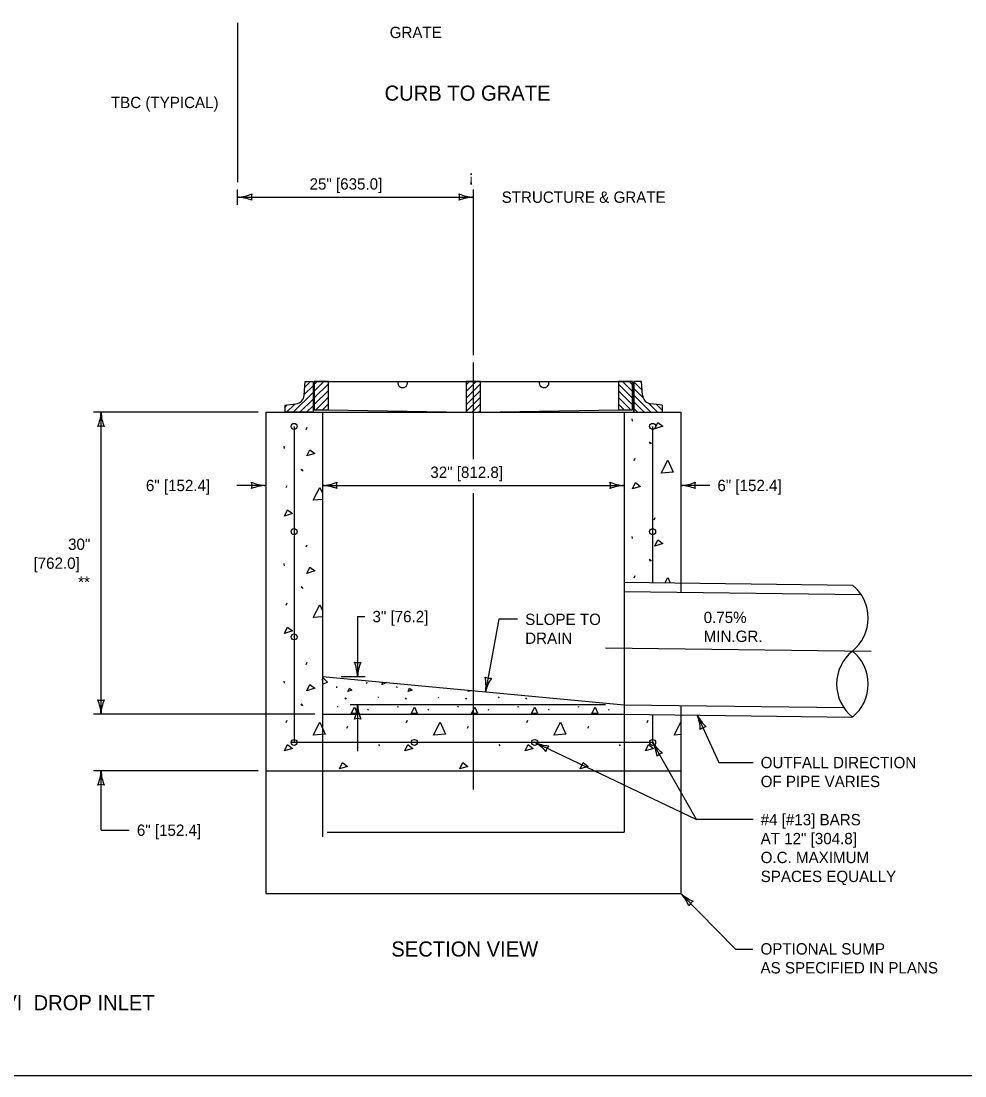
# Model space of a CAD drawing. Extents: x 49991.4 to 50041.6, y 49987.6 to 50011.4.
# Drawn here: x 50003.39 to 50008.39, y 49987.8 to 49993.39 of the extents above; entities that cross this region are included whole.
import ezdxf

# ---------------------------------------------------------------- set-up
doc = ezdxf.new("R2010")
doc.units = 0
for name, color, linetype in [('Level 1', 7, 'Continuous'), ('Level 2', 7, 'Continuous'), ('Level 3', 7, 'Continuous'), ('Level 4', 7, 'Continuous'), ('Level 5', 7, 'Continuous')]:
    doc.layers.add(name, color=color, linetype=linetype)

msp = doc.modelspace()

# ---------------------------------------------------------------- linework, layer by layer
at = {"layer": 'Level 1'}
for p, q in [((50004.5386, 49993.3789), (50004.5386, 49992.5353)), ((50004.8923, 49991.4098), (50004.9386, 49991.4562)), ((50004.8953, 49991.4482), (50004.9254, 49991.4783)), ((50004.9449, 49991.4783), (50006.6324, 49991.4783)), ((50004.9449, 49991.4266), (50004.9966, 49991.4783)), ((50004.9449, 49991.4619), (50004.9613, 49991.4783)), ((50004.9449, 49991.3912), (50005.0199, 49991.4662)), ((50005.4136, 49991.4783), (50005.4136, 49991.4783)), ((50005.7511, 49991.4262), (50005.8033, 49991.4783)), ((50005.7511, 49991.4615), (50005.7679, 49991.4783)), ((50005.7511, 49991.3908), (50005.8261, 49991.4658)), ((50006.1636, 49991.4783), (50006.1636, 49991.4783)), ((50006.5574, 49991.465), (50006.6324, 49991.39)), ((50006.5794, 49991.4783), (50006.6324, 49991.4254)), ((50006.6148, 49991.4783), (50006.6324, 49991.4607)), ((50006.6386, 49991.3158), (50006.6386, 49991.4783)), ((50006.6387, 49991.4773), (50006.6832, 49991.4328)), ((50006.6387, 49991.4419), (50006.6886, 49991.3921)), ((50006.673, 49991.4783), (50006.6802, 49991.4711)), ((50004.8336, 49991.3158), (50004.9386, 49991.4208)), ((50004.869, 49991.3158), (50004.9386, 49991.3855)), ((50004.9449, 49991.3559), (50005.0199, 49991.4309)), ((50004.9527, 49991.3283), (50005.0199, 49991.3955)), ((50005.7511, 49991.3555), (50005.8261, 49991.4305)), ((50005.7511, 49991.3201), (50005.8261, 49991.3951)), ((50006.5574, 49991.4297), (50006.6324, 49991.3547)), ((50006.5574, 49991.3943), (50006.6233, 49991.3283)), ((50006.6387, 49991.4066), (50006.7294, 49991.3158)), ((50004.7886, 49991.3529), (50004.8478, 49991.3597)), ((50004.7886, 49991.3415), (50004.8014, 49991.3543)), ((50004.7886, 49991.3529), (50004.7886, 49991.3158)), ((50004.7983, 49991.3158), (50004.8414, 49991.359)), ((50004.9043, 49991.3158), (50004.9386, 49991.3501)), ((50004.9881, 49991.3283), (50005.0199, 49991.3601)), ((50005.0199, 49991.3283), (50005.7511, 49991.3158)), ((50005.7822, 49991.3158), (50005.8261, 49991.3598)), ((50005.8261, 49991.3158), (50006.5574, 49991.3283)), ((50006.5574, 49991.359), (50006.588, 49991.3283)), ((50006.6387, 49991.3712), (50006.6941, 49991.3158)), ((50006.6387, 49991.3359), (50006.6587, 49991.3158)), ((50006.7174, 49991.3633), (50006.7648, 49991.3158)), ((50006.7598, 49991.3562), (50006.7886, 49991.3274)), ((50006.7886, 49991.3529), (50006.7886, 49991.3158)), ((50004.6886, 49991.3158), (50006.8886, 49991.3158)), ((50004.6886, 49991.3158), (50004.6886, 49989.7158)), ((50004.8252, 49991.3158), (50004.8253, 49991.3162)), ((50004.9886, 49991.3158), (50004.9886, 49989.7158)), ((50005.8175, 49991.3158), (50005.8261, 49991.3244)), ((50006.5886, 49991.3158), (50006.5886, 49989.7158)), ((50006.6286, 49991.2799), (50006.6299, 49991.2679)), ((50006.8886, 49991.3158), (50006.8886, 49990.362)), ((50004.8386, 49991.2408), (50004.8386, 49989.5665)), ((50004.9028, 49991.2238), (50004.9081, 49991.2358)), ((50006.7386, 49991.2408), (50006.7386, 49990.4139)), ((50006.7195, 49991.1588), (50006.7248, 49991.1508)), ((50004.7839, 49991.1357), (50004.7852, 49991.1237)), ((50006.7248, 49991.1558), (50006.7302, 49991.1478)), ((50006.6409, 49991.0601), (50006.6462, 49991.072)), ((50004.8748, 49991.0147), (50004.8801, 49991.0067)), ((50004.8801, 49991.0116), (50004.8855, 49991.0036)), ((50004.7962, 49990.9159), (50004.8015, 49990.9279)), ((50004.9886, 49990.8535), (50004.9401, 49990.8493)), ((50006.7475, 49990.7457), (50006.7528, 49990.7577)), ((50006.6286, 49990.6576), (50006.6299, 49990.6457)), ((50004.9028, 49990.6016), (50004.9081, 49990.6136)), ((50004.7839, 49990.5135), (50004.7852, 49990.5015)), ((50006.7195, 49990.5366), (50006.7248, 49990.5286)), ((50006.7248, 49990.5335), (50006.7302, 49990.5256)), ((50006.6409, 49990.4378), (50006.6462, 49990.4498)), ((50004.8748, 49990.3924), (50004.8801, 49990.3845)), ((50004.8801, 49990.3894), (50004.8855, 49990.3814)), ((50006.5886, 49990.4159), (50007.7977, 49990.4001)), ((50006.5886, 49990.3659), (50007.8438, 49990.3495)), ((50004.7962, 49990.2937), (50004.8015, 49990.3057)), ((50004.9886, 49990.2312), (50004.9401, 49990.2271)), ((50004.9028, 49989.9794), (50004.9081, 49989.9913)), ((50004.7839, 49989.8913), (50004.7852, 49989.8793)), ((50004.9886, 49989.9158), (50006.5886, 49989.7658)), ((50005.2234, 49989.8787), (50005.226, 49989.8847)), ((50005.3044, 49989.8719), (50005.3064, 49989.8861)), ((50005.3303, 49989.8838), (50005.305, 49989.8721)), ((50005.0627, 49989.862), (50005.0633, 49989.856)), ((50005.3817, 49989.862), (50005.3824, 49989.856)), ((50005.7615, 49989.8361), (50005.7649, 49989.8431)), ((50005.7794, 49989.8417), (50005.7615, 49989.8361)), ((50004.8748, 49989.7702), (50004.8801, 49989.7622)), ((50004.8801, 49989.7672), (50004.8855, 49989.7592)), ((50005.1081, 49989.8015), (50005.1108, 49989.7975)), ((50005.1108, 49989.8), (50005.1135, 49989.796)), ((50005.284, 49989.8015), (50005.2866, 49989.8075)), ((50005.4272, 49989.8015), (50005.4298, 49989.7975)), ((50005.4298, 49989.8), (50005.4325, 49989.796)), ((50005.603, 49989.8015), (50005.6057, 49989.8075)), ((50005.7462, 49989.8015), (50005.7489, 49989.7975)), ((50005.7489, 49989.8), (50005.7515, 49989.796)), ((50005.922, 49989.8015), (50005.9247, 49989.8075)), ((50006.0652, 49989.8015), (50006.0679, 49989.7975)), ((50006.0679, 49989.8), (50006.0706, 49989.796)), ((50006.5886, 49989.7658), (50007.7517, 49989.7506)), ((50006.8886, 49989.7619), (50006.8886, 49989.4158)), ((50004.6886, 49989.7158), (50004.6886, 49989.4158)), ((50004.9886, 49989.7158), (50006.5886, 49989.7158)), ((50005.0688, 49989.7521), (50005.0715, 49989.7581)), ((50005.23, 49989.7368), (50005.2327, 49989.7428)), ((50005.3879, 49989.7521), (50005.3905, 49989.7581)), ((50005.5491, 49989.7368), (50005.5517, 49989.7428)), ((50005.7069, 49989.7521), (50005.7096, 49989.7581)), ((50005.8681, 49989.7368), (50005.8708, 49989.7428)), ((50006.0259, 49989.7521), (50006.0286, 49989.7581)), ((50006.1871, 49989.7368), (50006.1898, 49989.7428)), ((50006.345, 49989.7521), (50006.3476, 49989.7581)), ((50006.5062, 49989.7368), (50006.5088, 49989.7428)), ((50006.5886, 49989.7158), (50007.7977, 49989.7)), ((50006.7386, 49989.7139), (50006.7386, 49989.5665)), ((50004.7962, 49989.6715), (50004.8015, 49989.6835)), ((50005.1186, 49989.6409), (50005.1239, 49989.6528)), ((50005.4343, 49989.6715), (50005.4396, 49989.6835)), ((50005.7566, 49989.6409), (50005.762, 49989.6528)), ((50006.0723, 49989.6715), (50006.0777, 49989.6835)), ((50006.3947, 49989.6409), (50006.4, 49989.6528)), ((50006.7104, 49989.6715), (50006.7157, 49989.6835)), ((50006.853, 49989.6049), (50006.8888, 49989.6727)), ((50006.8888, 49989.6078), (50006.8543, 49989.6049)), ((50004.8192, 49989.5665), (50006.7386, 49989.5665)), ((50005.2851, 49989.5556), (50005.2904, 49989.5476)), ((50005.9231, 49989.5556), (50005.9285, 49989.5476)), ((50006.5612, 49989.5556), (50006.5665, 49989.5476)), ((50004.6886, 49989.4158), (50006.8886, 49989.4158))]:
    msp.add_line(p, q, dxfattribs=at)
for points in [[(49999.3835, 49998.9992), (50016.7501, 49998.9992), (50016.7501, 49987.7988), (49999.3835, 49987.7988)], [(50004.9449, 49991.4783), (50004.9449, 49991.3283), (50005.0199, 49991.3283), (50005.0199, 49991.4783)], [(50005.7511, 49991.4783), (50005.7511, 49991.3158), (50005.8261, 49991.3158), (50005.8261, 49991.4783)], [(50006.5574, 49991.4783), (50006.5574, 49991.3283), (50006.6324, 49991.3283), (50006.6324, 49991.4783)]]:
    msp.add_lwpolyline(points, close=True, dxfattribs=at)
for points in [[(50004.8919, 49991.4054), (50004.8977, 49991.4783), (50004.8987, 49991.4783), (50004.9386, 49991.4783), (50004.9386, 49991.3158), (50004.7886, 49991.3158)], [(50006.6854, 49991.4054), (50006.6796, 49991.4783), (50006.6387, 49991.4783), (50006.6387, 49991.3158)], [(50006.7886, 49991.3529), (50006.7295, 49991.3597)], [(50006.6387, 49991.3158), (50006.7886, 49991.3158)], [(50006.7502, 49991.2281), (50006.7662, 49991.2614), (50006.7928, 49991.2414), (50006.7502, 49991.2281)], [(50004.9055, 49991.0839), (50004.9214, 49991.1172), (50004.9481, 49991.0973), (50004.9055, 49991.0839)], [(50006.7835, 49990.9935), (50006.8194, 49991.0614), (50006.8474, 49990.9988), (50006.7848, 49990.9935)], [(50006.6316, 49990.9095), (50006.6476, 49990.9428), (50006.6742, 49990.9229), (50006.6316, 49990.9095)], [(50004.9388, 49990.8493), (50004.9747, 49990.9173), (50004.9886, 49990.8862)], [(50004.7869, 49990.7654), (50004.8029, 49990.7987), (50004.8295, 49990.7787), (50004.7869, 49990.7654)], [(50006.7502, 49990.6058), (50006.7662, 49990.6391), (50006.7928, 49990.6192), (50006.7502, 49990.6058)], [(50004.9055, 49990.4617), (50004.9214, 49990.495), (50004.9481, 49990.475), (50004.9055, 49990.4617)], [(50006.8054, 49990.4126), (50006.8194, 49990.4392), (50006.8315, 49990.4122)], [(50004.9388, 49990.2271), (50004.9747, 49990.295), (50004.9886, 49990.2639)], [(50004.7869, 49990.1432), (50004.8029, 49990.1765), (50004.8295, 49990.1565), (50004.7869, 49990.1432)], [(50004.9055, 49989.8395), (50004.9214, 49989.8728), (50004.9481, 49989.8528), (50004.9055, 49989.8395)], [(50004.9886, 49989.8953), (50004.9906, 49989.9099), (50005.0145, 49989.8853), (50004.9886, 49989.8733)], [(50005.1235, 49989.8361), (50005.1315, 49989.8528), (50005.1448, 49989.8428), (50005.1235, 49989.8361)], [(50005.4425, 49989.8361), (50005.4505, 49989.8528), (50005.4638, 49989.8428), (50005.4425, 49989.8361)], [(50005.1401, 49989.7188), (50005.1581, 49989.7528), (50005.1721, 49989.7215), (50005.1408, 49989.7188)], [(50005.4592, 49989.7188), (50005.4771, 49989.7528), (50005.4911, 49989.7215), (50005.4598, 49989.7188)], [(50005.7782, 49989.7188), (50005.7962, 49989.7528), (50005.8102, 49989.7215), (50005.7788, 49989.7188)], [(50006.0972, 49989.7188), (50006.1152, 49989.7528), (50006.1292, 49989.7215), (50006.0979, 49989.7188)], [(50006.4162, 49989.7188), (50006.4342, 49989.7528), (50006.4482, 49989.7215), (50006.4169, 49989.7188)], [(50004.9388, 49989.6049), (50004.9747, 49989.6728), (50005.0027, 49989.6102), (50004.9401, 49989.6049)], [(50005.5768, 49989.6049), (50005.6128, 49989.6728), (50005.6408, 49989.6102), (50005.5782, 49989.6049)], [(50006.2149, 49989.6049), (50006.2508, 49989.6728), (50006.2788, 49989.6102), (50006.2162, 49989.6049)], [(50004.7869, 49989.521), (50004.8029, 49989.5543), (50004.8295, 49989.5343), (50004.7869, 49989.521)], [(50005.4249, 49989.521), (50005.4409, 49989.5543), (50005.4676, 49989.5343), (50005.4249, 49989.521)], [(50006.063, 49989.521), (50006.079, 49989.5543), (50006.1056, 49989.5343), (50006.063, 49989.521)], [(50006.7011, 49989.521), (50006.7171, 49989.5543), (50006.7437, 49989.5343), (50006.7011, 49989.521)], [(50005.0789, 49989.4258), (50005.0949, 49989.4591), (50005.1215, 49989.4391), (50005.0789, 49989.4258)], [(50005.7169, 49989.4258), (50005.7329, 49989.4591), (50005.7596, 49989.4391), (50005.7169, 49989.4258)], [(50006.355, 49989.4258), (50006.371, 49989.4591), (50006.3976, 49989.4391), (50006.355, 49989.4258)]]:
    msp.add_lwpolyline(points, dxfattribs=at)
for centre in [(50004.8386, 49991.2408), (50006.7386, 49991.2408), (50004.8386, 49990.683), (50006.7386, 49990.683), (50004.8386, 49990.1252), (50004.8386, 49989.5658), (50005.4761, 49989.5658), (50006.1136, 49989.5658), (50006.7386, 49989.5658)]:
    msp.add_circle(centre, 0.0159, dxfattribs=at)
for centre, radius, start, end in [((50005.4136, 49991.4722), 0.0258, 166.0941, 13.9059), ((50006.1636, 49991.4722), 0.0258, 166.0941, 13.9059), ((50004.8421, 49991.4094), 0.05, 276.5819, 355.4972), ((50006.7352, 49991.4094), 0.05, 184.5028, 263.4181), ((50007.6564, 49990.2251), 0.2249, 308.9152, 51.0848), ((50007.9389, 49989.8751), 0.2249, 128.9152, 231.0848), ((50007.6564, 49989.8751), 0.2249, 308.9152, 51.0848)]:
    msp.add_arc(centre, radius, start, end, dxfattribs=at)
at = {"layer": 'Level 3'}
for p, q in [((50004.5386, 49992.4153), (50004.5386, 49992.4953)), ((50004.5386, 49992.4553), (50005.7886, 49992.4553)), ((50005.7886, 49991.6183), (50005.7886, 49992.4953)), ((50004.6486, 49991.3158), (50003.7749, 49991.3158)), ((50003.8149, 49989.7158), (50003.8149, 49991.3158)), ((50004.6886, 49990.9275), (50004.5352, 49990.9275)), ((50004.9886, 49990.9275), (50006.5886, 49990.9275)), ((50007.0421, 49990.9275), (50006.8886, 49990.9275)), ((50005.1749, 49990.233), (50005.1749, 49989.9158)), ((50005.1749, 49990.233), (50005.2139, 49990.233)), ((50005.9232, 49990.2183), (50005.8537, 49989.8347)), ((50006.0232, 49990.2183), (50005.9232, 49990.2183)), ((50005.0886, 49989.9158), (50005.2149, 49989.9158)), ((50006.4886, 49989.7658), (50005.1349, 49989.7658)), ((50005.1749, 49989.7658), (50005.1749, 49989.519)), ((50004.9486, 49989.7158), (50003.7749, 49989.7158)), ((50006.9752, 49989.7108), (50007.0902, 49989.4592)), ((50006.1124, 49989.5665), (50006.972, 49989.1567)), ((50006.972, 49989.1567), (50006.7386, 49989.5665)), ((50007.0902, 49989.4592), (50007.2714, 49989.4592)), ((50004.6486, 49989.4158), (50003.7749, 49989.4158)), ((50003.8149, 49989.1008), (50003.8149, 49989.4158)), ((50007.2714, 49989.1567), (50006.972, 49989.1567)), ((50003.8149, 49989.1008), (50003.9649, 49989.1008)), ((50006.8886, 49988.7658), (50007.1783, 49988.4696)), ((50007.1783, 49988.4696), (50007.2706, 49988.4696))]:
    msp.add_line(p, q, dxfattribs=at)
for centre, radius, start, end in [((50004.5271, 49992.688), 0.233, 272.8273, 292.0772), ((50004.5295, 49992.2332), 0.2223, 67.456, 87.6395), ((50004.6668, 49992.4553), 0.0548, 162.1388, 197.8612), ((50005.7978, 49992.6775), 0.2223, 247.456, 267.6395), ((50005.6604, 49992.4553), 0.0548, 342.1388, 17.8612), ((50005.8001, 49992.2226), 0.233, 92.8273, 112.0772), ((50003.5928, 49991.325), 0.2223, 337.456, 357.6395), ((50004.0476, 49991.3273), 0.233, 182.8273, 202.0772), ((50003.8149, 49991.1876), 0.0548, 72.1388, 107.8612), ((50004.6978, 49991.1496), 0.2223, 247.456, 267.6395), ((50004.5604, 49990.9275), 0.0548, 342.1388, 17.8612), ((50004.9771, 49991.1602), 0.233, 272.8273, 292.0772), ((50005.1168, 49990.9275), 0.0548, 162.1388, 197.8612), ((50006.5978, 49991.1496), 0.2223, 247.456, 267.6395), ((50006.4604, 49990.9275), 0.0548, 342.1388, 17.8612), ((50006.8771, 49991.1602), 0.233, 272.8273, 292.0772), ((50007.0168, 49990.9275), 0.0548, 162.1388, 197.8612), ((50004.7001, 49990.6948), 0.233, 92.8273, 112.0772), ((50004.9795, 49990.7054), 0.2223, 67.456, 87.6395), ((50006.6001, 49990.6948), 0.233, 92.8273, 112.0772), ((50006.8795, 49990.7054), 0.2223, 67.456, 87.6395), ((50005.1749, 49990.0441), 0.0548, 252.1388, 287.8612), ((50004.9422, 49989.9044), 0.233, 2.8273, 22.0772), ((50005.3971, 49989.9067), 0.2223, 157.456, 177.6395), ((50005.8765, 49989.9609), 0.0548, 241.8645, 277.5869), ((50005.6226, 49989.8649), 0.233, 352.553, 11.8029), ((50006.0706, 49989.7861), 0.2223, 147.1817, 167.3652), ((50003.8149, 49989.8441), 0.0548, 252.1388, 287.8612), ((50003.5822, 49989.7044), 0.233, 2.8273, 22.0772), ((50004.037, 49989.7067), 0.2223, 157.456, 177.6395), ((50004.9528, 49989.775), 0.2223, 337.456, 357.6395), ((50005.4076, 49989.7773), 0.233, 182.8273, 202.0772), ((50006.7693, 49989.6268), 0.2223, 2.0239, 22.2074), ((50007.182, 49989.818), 0.233, 207.3952, 226.645), ((50005.1749, 49989.6376), 0.0548, 72.1388, 107.8612), ((50007.0285, 49989.5942), 0.0548, 96.7067, 132.4291), ((50006.006, 49989.3713), 0.2223, 41.2211, 61.4046), ((50006.205, 49989.7804), 0.233, 246.5924, 265.8422), ((50006.2274, 49989.5099), 0.0548, 135.9039, 171.6263), ((50006.5419, 49989.463), 0.2223, 7.567, 27.7505), ((50006.9342, 49989.6932), 0.233, 212.9383, 232.1882), ((50006.8029, 49989.4556), 0.0548, 102.2498, 137.9722), ((50003.5928, 49989.425), 0.2223, 337.456, 357.6395), ((50004.0476, 49989.4273), 0.233, 182.8273, 202.0772), ((50003.8149, 49989.2876), 0.0548, 72.1388, 107.8612), ((50006.7253, 49988.615), 0.2223, 22.5571, 42.7406), ((50007.0447, 49988.9388), 0.233, 227.9284, 247.1783), ((50006.9794, 49988.6753), 0.0548, 117.2399, 152.9623)]:
    msp.add_arc(centre, radius, start, end, dxfattribs=at)
at = {"layer": 'Level 4'}
for p, q in [((50004.9886, 49989.7158), (50004.9886, 49989.0658)), ((50006.5886, 49989.7158), (50006.5886, 49989.0908)), ((50004.6886, 49989.4158), (50004.6886, 49989.0908)), ((50006.8886, 49989.4158), (50006.8886, 49988.7658)), ((50004.6886, 49989.0908), (50004.6886, 49988.7658)), ((50005.0136, 49989.0908), (50006.5886, 49989.0908)), ((50004.6886, 49988.7658), (50006.8886, 49988.7658))]:
    msp.add_line(p, q, dxfattribs=at)
at = {"layer": 'Level 5'}
for p, q in [((50005.7886, 49991.0675), (50005.7886, 49991.5783)), ((50005.7886, 49989.3158), (50005.7886, 49990.8875)), ((50006.4886, 49990.0672), (50007.8977, 49990.0488))]:
    msp.add_line(p, q, dxfattribs=at)

# ---------------------------------------------------------------- texts
at = {"layer": 'Level 2'}
for s, height, p in [('GRATE', 0.06, (50005.345, 49993.2983)), ('CURB TO GRATE', 0.08, (50005.3178, 49992.9666)), ('TBC (TYPICAL)', 0.06, (50003.8674, 49992.9271)), ('25" [635.0]', 0.06, (50004.9204, 49992.4953)), ('¡', 0.06, (50005.7635, 49992.5353)), ('STRUCTURE & GRATE', 0.06, (50005.9386, 49992.4253)), ('32" [812.8]', 0.06, (50005.5605, 49990.9675)), ('6" [152.4]', 0.06, (50004.0527, 49990.8975)), ('6" [152.4]', 0.06, (50007.0821, 49990.8975)), ('30" ', 0.06, (50003.6403, 49990.586)), ('[762.0]', 0.06, (50003.457, 49990.4858)), ('**', 0.06, (50003.6935, 49990.3856)), ('3" [76.2]', 0.06, (50005.2539, 49990.203)), ('SLOPE TO', 0.06, (50006.0632, 49990.1883)), ('0.75% ', 0.06, (50007.0094, 49990.1985)), ('MIN.GR.', 0.06, (50007.0094, 49990.0983)), ('DRAIN', 0.06, (50006.0632, 49990.0881)), ('OUTFALL DIRECTION', 0.06, (50007.3114, 49989.4292)), ('OF PIPE VARIES', 0.06, (50007.3114, 49989.329)), ('#4 [#13] BARS', 0.06, (50007.3114, 49989.1267)), ('6" [152.4]', 0.06, (50004.0049, 49989.0708)), ('AT 12" [304.8]', 0.06, (50007.3114, 49989.0265)), ('O.C. MAXIMUM', 0.06, (50007.3114, 49988.9263)), ('SPACES EQUALLY', 0.06, (50007.3114, 49988.8261)), ('SECTION VIEW', 0.08, (50005.3536, 49988.4313)), ('OPTIONAL SUMP ', 0.06, (50007.3106, 49988.442)), ('AS SPECIFIED IN PLANS', 0.06, (50007.3106, 49988.3418)), ('TYPE III  AND VI  DROP INLET', 0.08, (50002.5835, 49988.1468))]:
    msp.add_text(s, height=height, dxfattribs=at).set_placement(p)

doc.saveas('drawing.dxf')
